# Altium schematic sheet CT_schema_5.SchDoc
size 218 x 258 mm
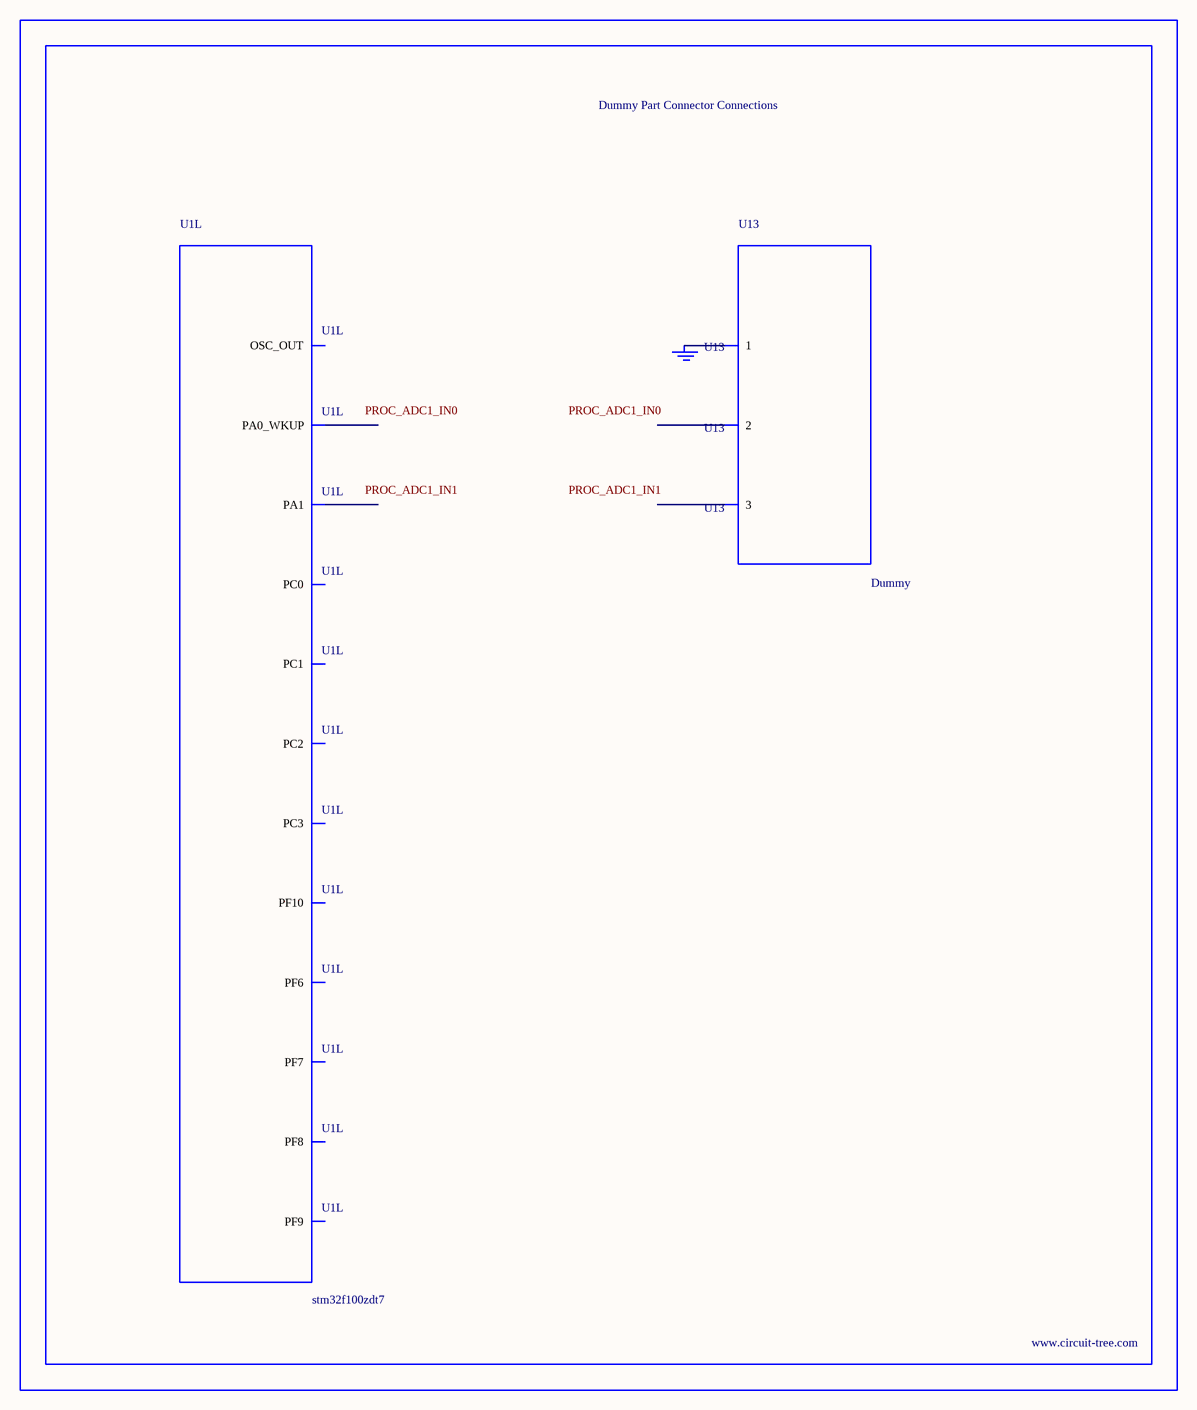
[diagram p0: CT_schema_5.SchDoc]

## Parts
BORDER4  (no value)
GND_INSTANCE_4_0  (no value)
U1  stm32f100zdt7  [LQFP144]  (part L of 12)
U13  Dummy  [DUMMY_PACKAGE_145]

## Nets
NetGND_INSTANCE_4_0_0: GND_INSTANCE_4_0.0(GND) U13.1

Not connected (* = marked no-connect by the designer): U1 18(PF6) 19(PF7) 20(PF8) 21(PF9) 22(PF10) 24(OSC_OUT) 26(PC0) 27(PC1) 28(PC2) 29(PC3) 34(PA0_WKUP) 35(PA1); U13 2 3

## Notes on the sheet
- Labels drawn without touching a wire or pin: PROC_ADC1_IN0, PROC_ADC1_IN1

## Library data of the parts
BORDER4 = BORDER_PAGE4
GND_INSTANCE_4_0 = GND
